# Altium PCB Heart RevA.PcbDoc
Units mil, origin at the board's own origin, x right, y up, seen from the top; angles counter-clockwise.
Board outline 1999.01 x 2099.61 mil, 2 copper layers (Top Copper, Bottom Copper), stack 61.811 mil thick; 52 components, 27 nets, 146 pads, 19 vias.
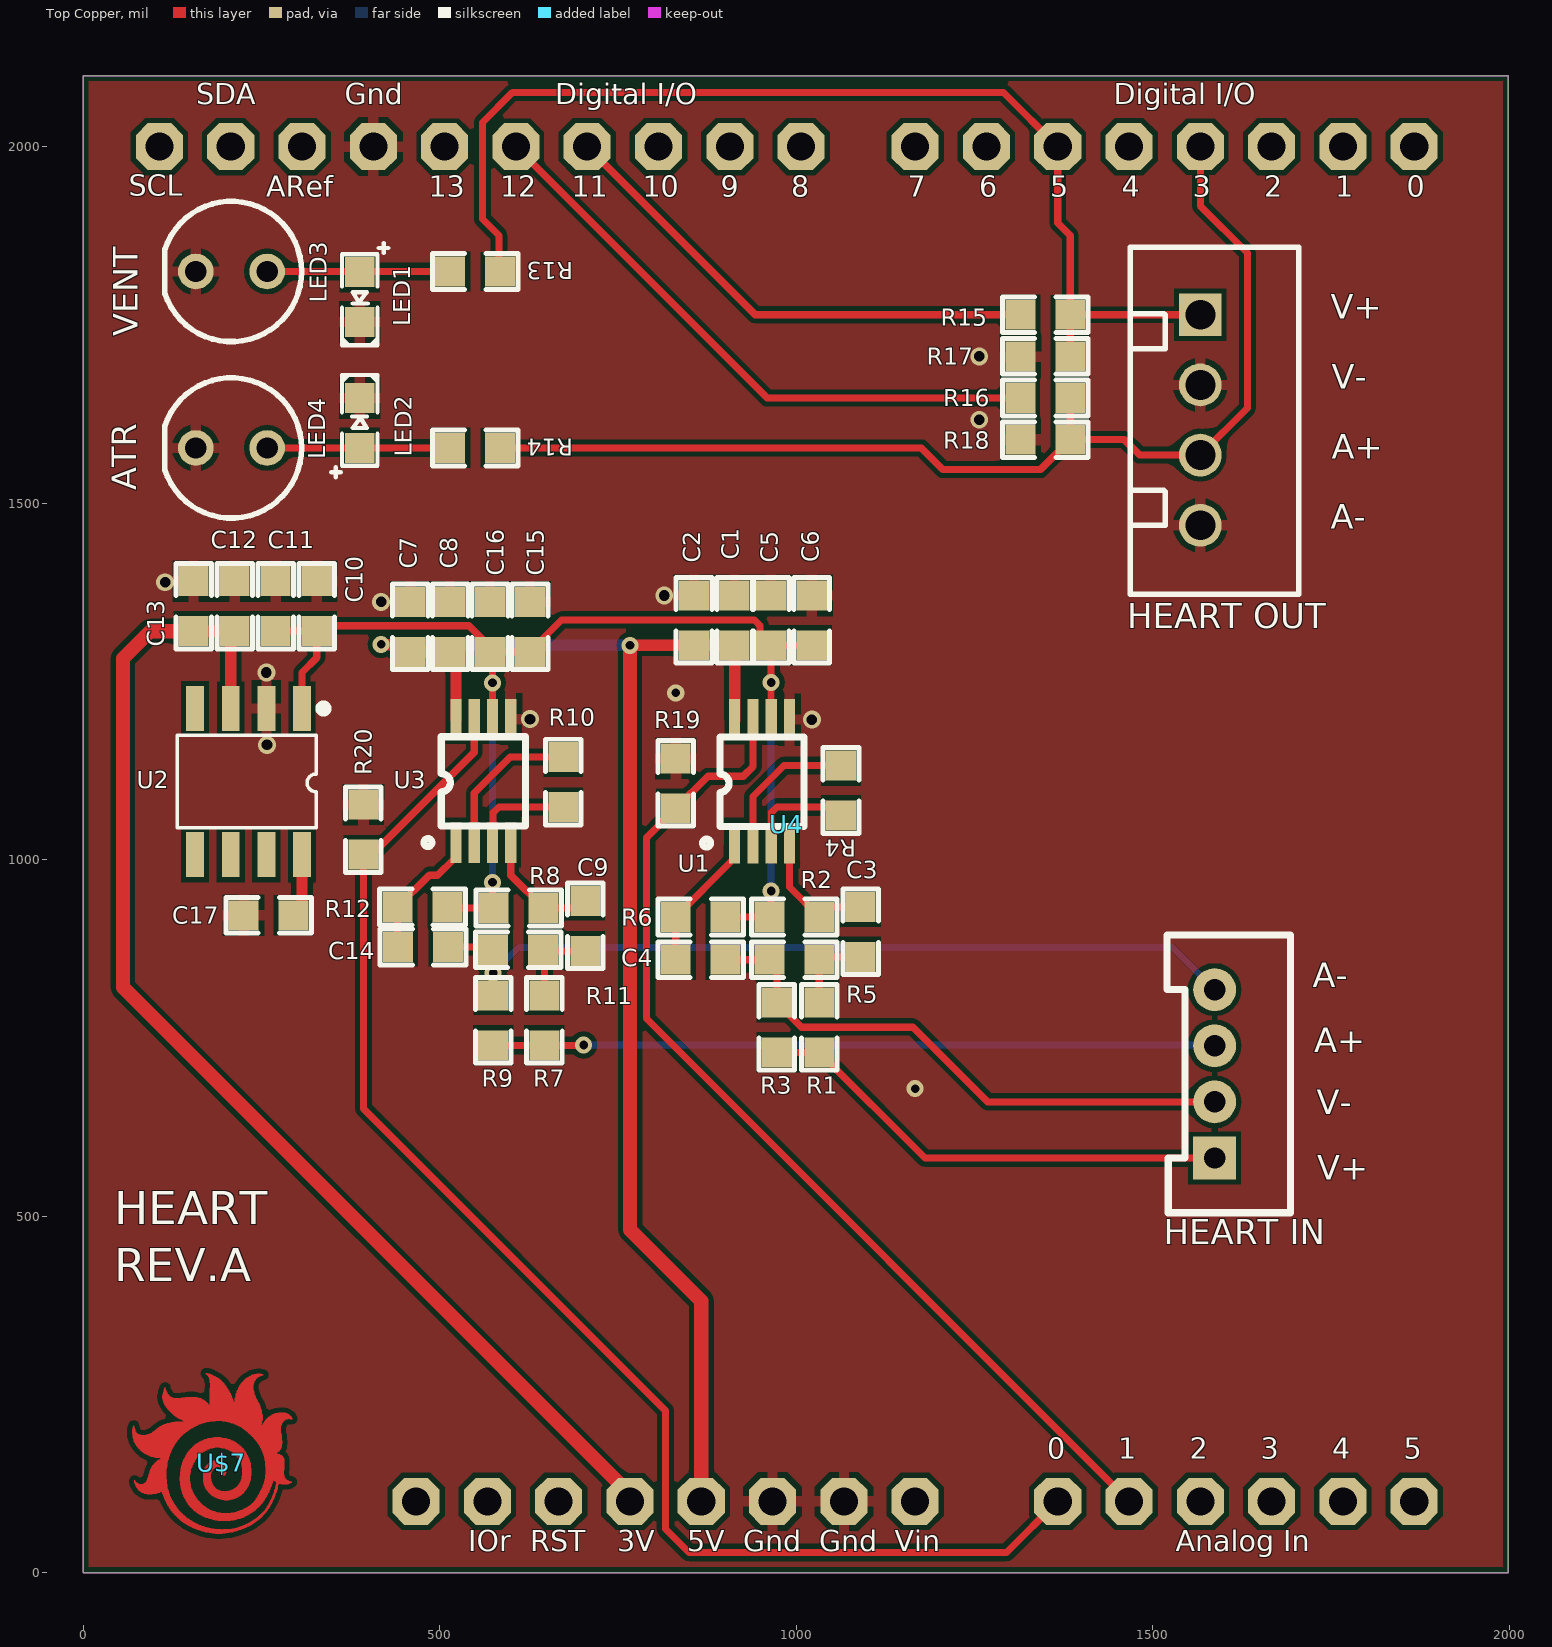
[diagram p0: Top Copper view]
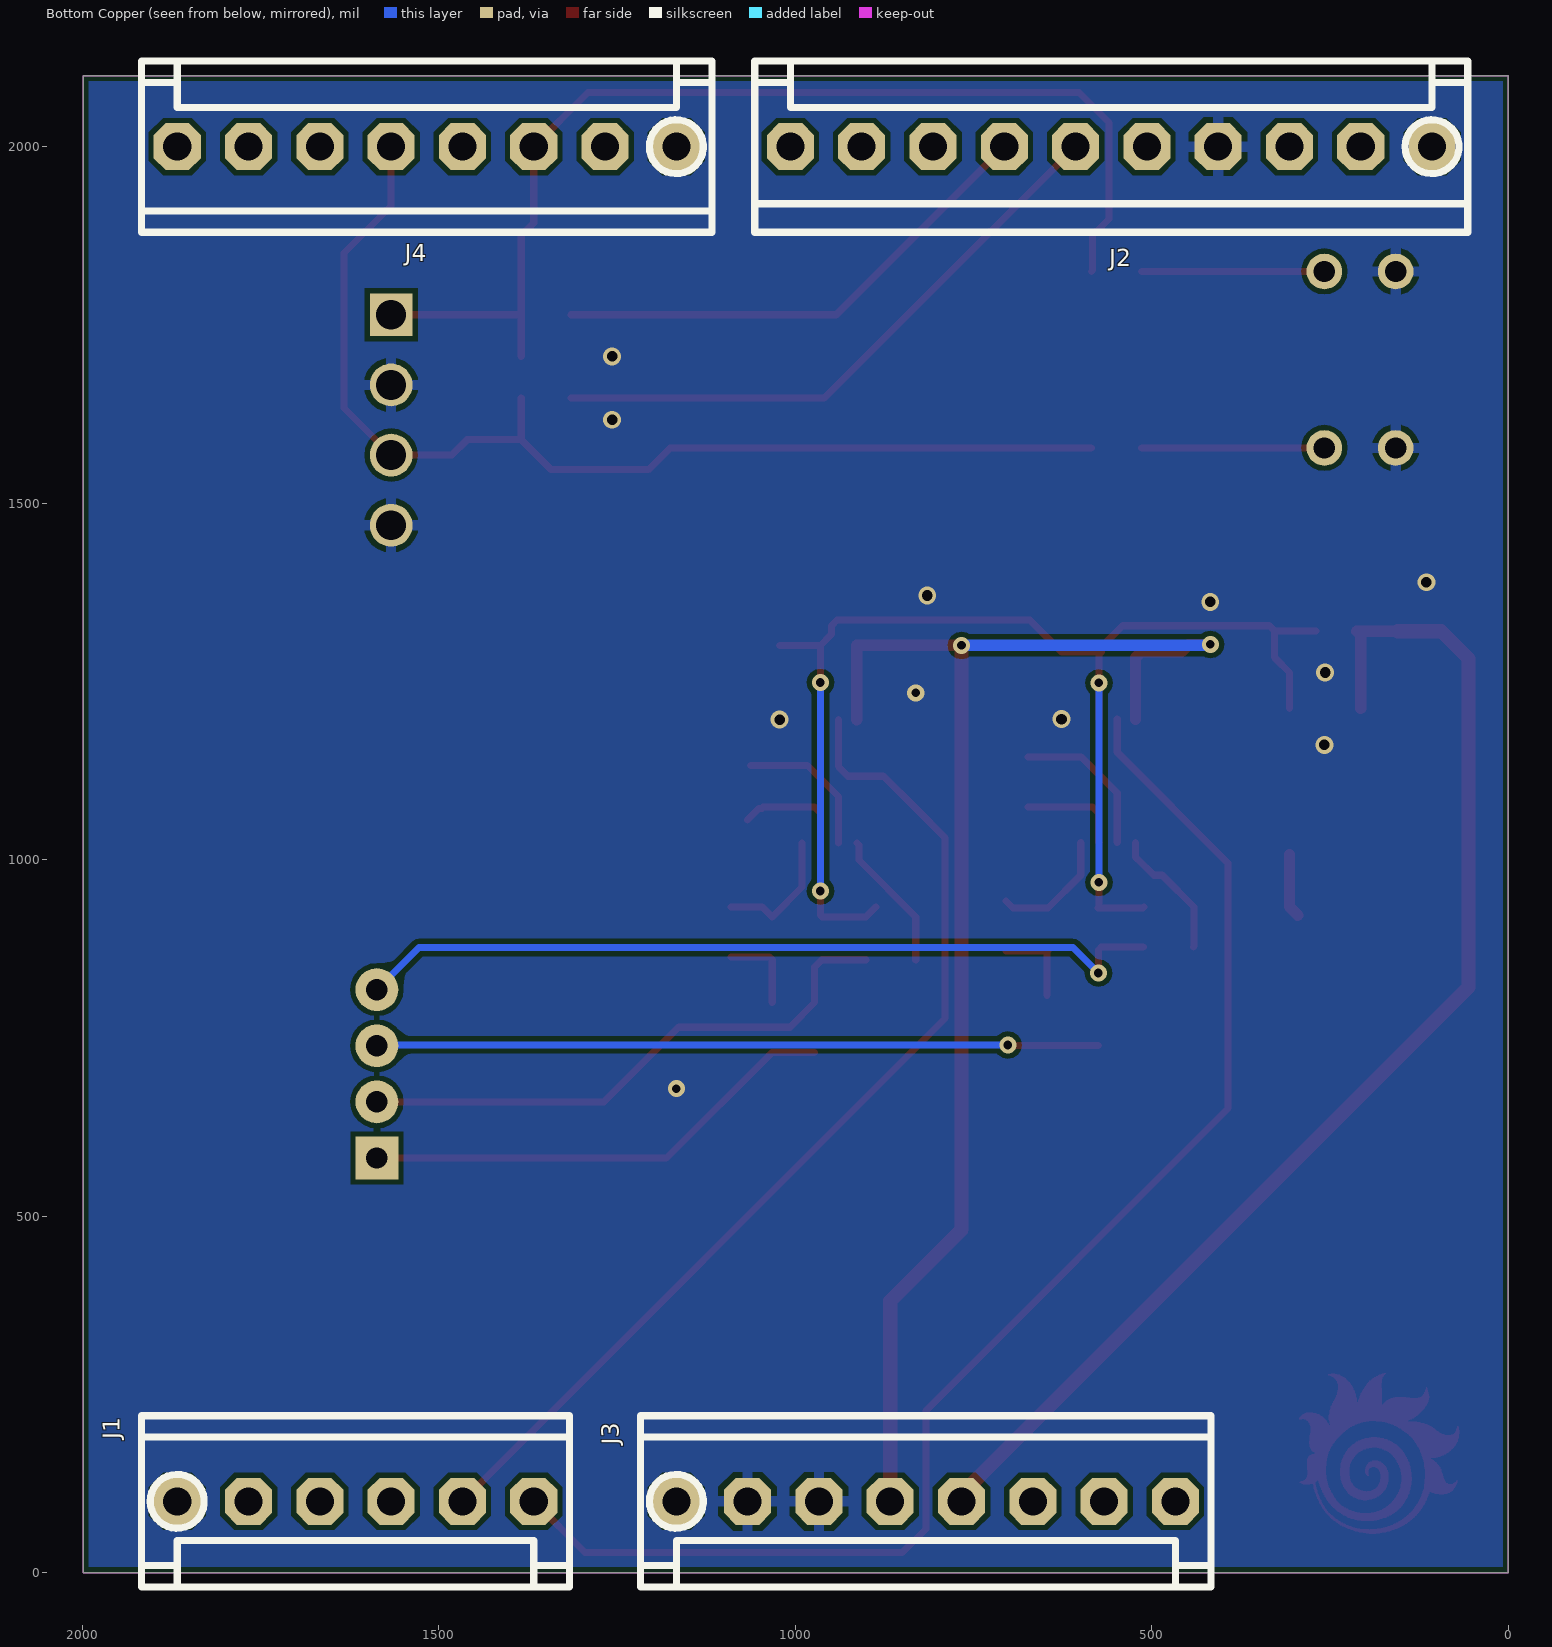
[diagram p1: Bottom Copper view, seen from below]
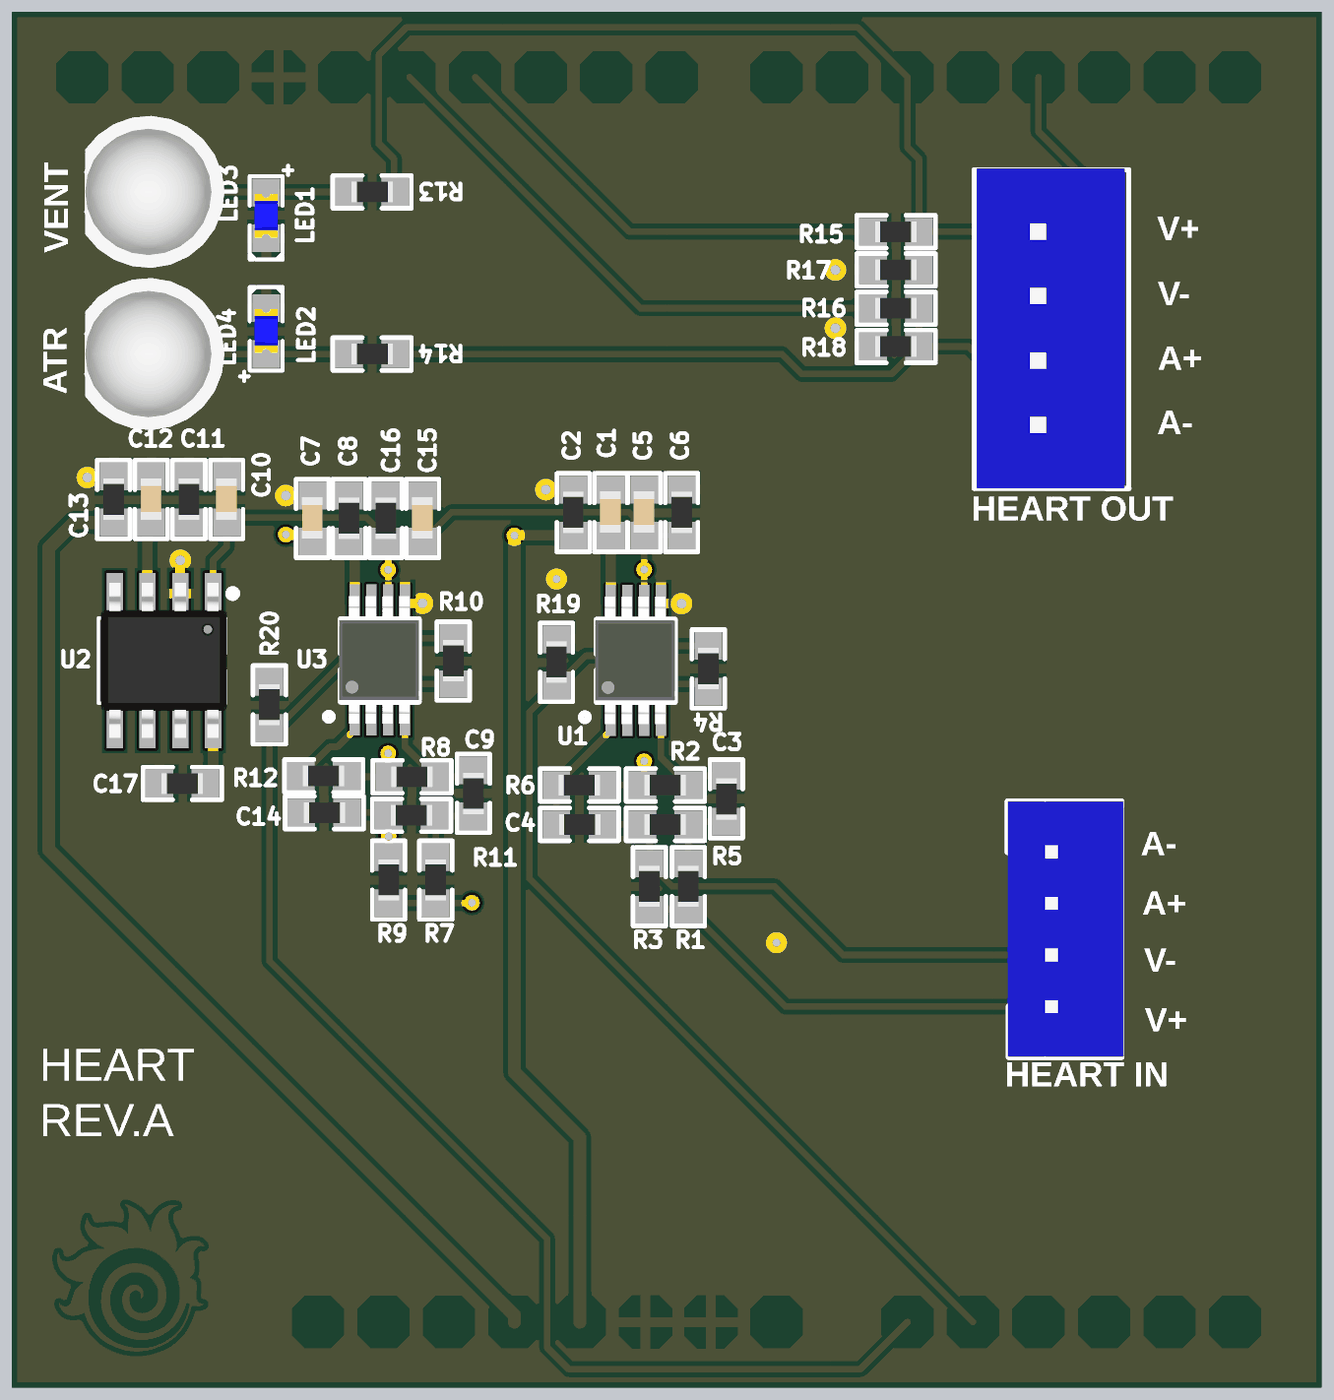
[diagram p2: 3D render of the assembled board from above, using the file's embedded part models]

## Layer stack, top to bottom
Top Mask: solder mask 0.5906, Solder Resist, Dk 3.8
Top Copper: signal copper 1.378
Dielectric 1: prepreg 3.937, 2313, Dk 4.05
Core: core 51.1811, FR-4, Dk 4.5
Dielectric 2: prepreg 3.937, 2313, Dk 4.05
Bottom Copper: signal copper 1.378
Bottom Mask: solder mask 0.5906, Solder Resist, Dk 3.8

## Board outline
0,0 0,2099.61 1999.01,2099.61 1999.01,0

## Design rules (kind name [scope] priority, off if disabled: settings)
AssemblyTestPointUsage [All] p1 off:
AssemblyTestpoint [All] p1 off: testpointundercomponent=TRUE minsize=40 maxsize=100 preferedsize=60 minholesize=0 maxholesize=40 preferedholesize=32 testpointgrid=1 usegrid=TRUE gridtolerance=0.01 allowsidetop=TRUE allowsidebottom=TRUE
Clearance Clearance_poly [InPolygon vs InPolygon] p1: gap=10 ignorepadtopadclearanceinfootprint=FALSE
Clearance [All] p2: gap=7 ignorepadtopadclearanceinfootprint=FALSE
ComponentClearance [All] p1 off: gap=10 collisioncheckmode=3 verticalgap=10 showdistances=FALSE
DiffPairsRouting [All] p1 off: maxlimit=10 minlimit=10 mostfreqgap=10 toplayer_minwidth=15 toplayer_maxwidth=15 toplayer_prefwidth=15 bottomlayer_minwidth=15 bottomlayer_maxwidth=15 bottomlayer_prefwidth=15 maxuncoupledlength=500
FabricationTestPointUsage [All] p1 off: valid=0 allowmultiple=FALSE
FabricationTestpoint [All] p1 off: side=3 testpointundercomponent=TRUE minsize=40 maxsize=100 preferedsize=60 minholesize=0 maxholesize=40 preferedholesize=32 testpointgrid=1 allowsidetop=TRUE allowsidebottom=TRUE usegrid=TRUE gridtolerance=0.01
FanoutControl Fanout_BGA [IsBGA] p1 off: bgadir=Out bgaviamode=Centered fanoutstyle=Auto fanoutdirection=Alternating viagrid=1 // Fanout_BGA (Default Rule)
FanoutControl Fanout_LCC [IsLCC] p2 off: bgadir=Out bgaviamode=Centered fanoutstyle=Auto fanoutdirection=Alternating viagrid=1 // Fanout_LCC (Default Rule)
FanoutControl Fanout_SOIC [IsSOIC] p3 off: bgadir=Out bgaviamode=Centered fanoutstyle=Auto fanoutdirection=Alternating viagrid=1 // Fanout_SOIC (Default Rule)
FanoutControl Fanout_Small [(CompPinCount < 5)] p4 off: bgadir=Out bgaviamode=Centered fanoutstyle=Auto fanoutdirection=OutThenIn viagrid=1 // Fanout_Small (Default Rule)
FanoutControl Fanout_Default [All] p5 off: bgadir=Out bgaviamode=Centered fanoutstyle=Auto fanoutdirection=Alternating viagrid=1 // Fanout_Default (Default Rule)
Height [All] p1 off: minheight=0 maxheight=1000 prefheight=500
HoleSize [All] p1: absolutevalues=TRUE maxlimit=236.22 minlimit=0.98 maxpercent=80.000 minpercent=20.000
MinimumSolderMaskSliver [All] p1 off: minsoldermaskwidth=10
PolygonConnect PolygonConnect_via [IsVia] p1: connectstyle=Direct reliefconductorwidth=10 reliefentries=4 polygonreliefangle="90 Angle" airgapwidth=10
PolygonConnect [All] p2: connectstyle=Relief reliefconductorwidth=15 reliefentries=4 polygonreliefangle="90 Angle" airgapwidth=8
RoutingPriority [All] p1 off: routingpriority=0
RoutingTopology [All] p1 off: topology=Shortest
RoutingVias [All] p1: holewidth=15 width=25 viastyle="Through Hole" minholewidth=12 minwidth=24 maxholewidth=60 maxwidth=80
SilkToSilkClearance [All] p1 off: silktosilkclearance=10
SilkToSolderMaskClearance [IsPad] p1 off: minsilkscreentomaskgap=10 clearancetoexposedcopper=TRUE
SolderMaskExpansion [All] p1: expansion=4 istentingtop=FALSE
UnRoutedNet UnRoutedNet_signal [All] p1:
UnpouredPolygon [All] p1 off:
Width [All] p1: maxlimit=80 minlimit=8 preferedwidth=8
10 further rules are at their usual default settings.

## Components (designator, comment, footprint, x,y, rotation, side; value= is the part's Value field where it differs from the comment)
C1 "0.1uF" 0603_N_1MM 913.79,1370.54 r270 top value=CL10B104KB8NNNL
C2 "1uF" 0603_N 856.74,1370.54 r270 top value=CL10B105KQ8NNNC
C3 "3300pF" 0603_N 1090.5,863.6 r90 top value=885012006016
C4 "3300pF" 0603_N 901.22,859.6 r180 top value=885012006016
C5 "0.1uF" 0603_N_1MM 964.99,1370.54 r270 top value=CL10B104KB8NNNL
C6 "1uF" 0603_N 1022.09,1370.54 r270 top value=CL10B105KQ8NNNC
C7 "0.1uF" 0603_N_1MM 458.73,1361.56 r270 top value=CL10B104KB8NNNL
C8 "1uF" 0603_N 514.73,1361.56 r270 top value=CL10B105KQ8NNNC
C9 "3300pF" 0603_N 704.43,872.02 r90 top value=885012006016
C10 "0.1uF" 0603_N_1MM 327.73,1390.54 r270 top value=CL10B104KB8NNNL
C11 "1uF" 0603_N 270.15,1390.54 r270 top value=CL10B105KQ8NNNC
C12 "0.1uF" 0603_N_1MM 212.57,1390.54 r270 top value=CL10B104KB8NNNL
C13 "1uF" 0603_N 154.99,1390.54 r270 top value=CL10B105KQ8NNNC
C14 "3300pF" 0603_N 511.72,877.48 r180 top value=885012006016
C15 "0.1uF" 0603_N_1MM 626.73,1361.56 r270 top value=CL10B104KB8NNNL
C16 "1uF" 0603_N 570.73,1361.56 r270 top value=CL10B105KQ8NNNC
C17 "1uF" 0603_N 225.15,922.02 r0 top value=CL10B105KQ8NNNC
"HEART IN" "B4B-PH-K-S" B4B-PH-K-S 1587,620.83 r90 top
"HEART OUT" "B4B-XH-A" B4B-XH-A 1567,1764.28 r270 top value=B4B-XH-A(LF)(SN)
J1 "LHS-06-TS" LHS-00-TS_OUTLINE 1867,100 r0 bottom
J2 "LHS-10-TS" LHS-10-TS_OUTLINE 107,2000 r180 bottom
J3 "LHS-08-TS" LHS-08-TS_OUTLINE 1167,100 r0 bottom
J4 "LHS-08-TS" LHS-08-TS_OUTLINE 1167,2000 r180 bottom
LED1 "VLMB1300-GS08" LED_0603 388,1824 r270 top
LED2 "SML-D12V1WT86" LED_0603 388,1577.47 r90 top
LED3 "151051BS04000" LED_5MM 208.2,1825 r0 top
LED4 "151051RS11000" LED_5MM 208.2,1577.47 r0 top
R1 "75K" 0603_N_RES 1032.5,799.6 r270 top value=RC0603FR-0775KL
R2 "162K" 0603_N_RES 962.5,919.6 r0 top value=RC0603FR-07162KL
R3 "1K" 0603_N_RES 973.1,799.6 r270 top value=RC0603FR-071KL
R4 "49.9K" 0603_N_RES 1063,1132 r270 top value=RC0603FR-0749K9L
R5 "49.9K" 0603_N_RES 962.5,859.6 r0 top value=RC0603FR-0749K9L
R6 "162K" 0603_N_RES 831.22,919.6 r0 top value=RC0603FR-07162KL
R7 "75K" 0603_N_RES 647.01,809.48 r270 top value=RC0603FR-0775KL
R8 "162K" 0603_N_RES 575.73,932.22 r0 top value=RC0603FR-07162KL
R9 "1K" 0603_N_RES 575.01,809.48 r270 top value=RC0603FR-071KL
R10 "49.9K" 0603_N_RES 673.6,1143.88 r270 top value=RC0603FR-0749K9L
R11 "49.9K" 0603_N_RES 575.01,873.48 r0 top value=RC0603FR-0749K9L
R12 "162K" 0603_N_RES 441,933.6 r0 top value=RC0603FR-07162KL
R13 "100" 0603_N_RES 584.73,1825 r180 top value=RC0603FR-07100RL
R14 "150" 0603_N_RES 584.73,1577.47 r180 top value=RC0603FR-07150RL
R15 "100K" 0603_N_RES 1314.57,1764.28 r0 top value=RC0603FR-07100KL
R16 "100K" 0603_N_RES 1314.57,1647.47 r0 top value=RC0603FR-07100KL
R17 "1K" 0603_N_RES 1314.57,1705.87 r0 top value=RC0603FR-071KL
R18 "1K" 0603_N_RES 1314.57,1589.06 r0 top value=RC0603FR-071KL
R19 "49.9K" 0603_N_RES 831.22,1142 r270 top value=RC0603FR-0749K9L
R20 "49.9K" 0603_N_RES 393,1077 r270 top value=RC0603FR-0749K9L
U1 "AD8220" MSOP8_0.65mm_DGK 913.81,1023.22 r90 top value=AD8220ARMZ-R7
U2 "TLE2426CDR" SOIC8_SMTC 307,1212 r270 top
U3 "AD8220" MSOP8_0.65mm_DGK 523.01,1023.88 r90 top value=AD8220ARMZ-R7
U4 "ARDUINO_R3" ARDUINOR3 -633,0 r0 top value=n/a
U$7 "" FIREBALL 194,155 r0 top

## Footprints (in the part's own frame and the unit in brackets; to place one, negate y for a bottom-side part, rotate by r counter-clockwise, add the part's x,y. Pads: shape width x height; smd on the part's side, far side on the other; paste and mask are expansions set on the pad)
0603_N [mil]
  rect 42x42 smd mask+0: 1(0,0) 2(70,0)
  silkscreen extent -25,-25 95,25, body extent 3,-16 66,16, height 19
0603_N_1MM [mil] "Full height"
  rect 42x42 smd mask+0: 1(0,0) 2(70,0)
  silkscreen extent -25,-25 95,25, body extent 3,-16 66,15, height 31
0603_N_RES [mil]
  rect 42x42 smd mask+0: 1(0,0) 2(70,0)
  silkscreen extent -25,-25 95,25, body extent 3,-16 66,16, height 19
ARDUINOR3 [mil] "ARDUINOR3"
  oct 66x66 / inner round 0 / far side oct 66x66 hole 39.37: 3V(1400,100) 5V(1500,100) A0(2000,100) A1(2100,100) A2(2200,100) A3(2300,100) A4(2400,100) A5(2500,100) AREF(940,2000) D0(2500,2000) D1(2400,2000) D2(2300,2000) D3(2200,2000) D4(2100,2000) D5(2000,2000) D6(1900,2000) D7(1800,2000) D8(1640,2000) D9(1540,2000) D10(1440,2000) D11(1340,2000) D12(1240,2000) D13(1140,2000) GND(1040,2000) GND1(1700,100) GND2(1600,100) IOREF(1200,100) RESERVED(1100,100) RESET(1300,100) SDA(840,2000) VIN(1800,100)
  oct 66x66 hole 39.37: SCL(740,2000)
B4B-PH-K-S [mil]
  rect 60x60 / inner round 60 / far side rect 60x60 hole 30: 1(-39.37,0)
  round 60 hole 30: 2(39.37,0) 3(118.11,0) 4(196.85,0)
  silkscreen extent -116,-106 274,67, body extent -116,-110 274,67, height 236
B4B-XH-A [mil]
  rect 60x60 hole 42: 1(0,0)
  round 60 hole 42: 2(98.43,0) 3(196.85,0) 4(295.28,0)
  silkscreen extent -94,-98 392,138, body extent -96,-94 392,132, height 276
FIREBALL [mil] "FIREBALL"
  Top Copper drawing of 1562 lines, arcs and shapes, not listed
LED_5MM [mil]
  round 50 hole 30: A(49.8,0) K(-50.2,0)
  silkscreen extent -94,-98 98,98, body extent -96,-116 116,116, height 362
LED_0603 [mil]
  rect 42x42 smd mask+0: A(0,0) K(70,0)
  silkscreen extent -41,-25 102,40, body extent 2,-18 69,18, height 35
LHS-00-TS_OUTLINE [mil]
  silkscreen extent -550,-120 50,120, body extent -555,-125 55,125, height 394
LHS-08-TS_OUTLINE [mil]
  silkscreen extent -750,-120 50,120
LHS-10-TS_OUTLINE [mil]
  silkscreen extent -950,-120 50,120
MSOP8_0.65mm_DGK [mm]
  rect 1.45x0.4 smd: 1(0,0) 2(0,-0.65) 3(0,-1.3) 4(0,-1.95) 5(4.4,-1.95) 6(4.4,-1.3) 7(4.4,-0.65) 8(4.4,0)
  silkscreen extent -0.14,-2.48 3.77,1.14, body extent -0.27,-2.5 4.67,0.6, height 1.1
SOIC8_SMTC [mil]
  rect 63x25 smd: 1(0,0) 2(0,-50) 3(0,-100) 4(0,-150) 5(205,-150) 6(205,-100) 7(205,-50) 8(205,0)
  silkscreen extent -5,-175 167,35, body extent -16,-171 220,21, height 67

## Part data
C1 C5 C7 C10 C12 C15: library part CAP, "CAP CER 0.1UF 50V X7R 0603", Manufacturer=Samsung
C2 C6 C8 C11 C13 C16 C17: library part CAP, "CAP CER 1UF 6.3V X7R 0603", Manufacturer=Samsung
C3 C4 C9 C14: library part CAP, "CAP CER 3300PF 10V C0G/NP0 0603", Manufacturer="Würth Elektronik"
"HEART IN": library part "Header 4", "CONN HEADER VERT 4POS 2MM", Manufacturer=JST
"HEART OUT": library part "Header 4", "CONN HEADER VERT 4POS 2.5MM", Manufacturer=JST
J1: library part "SIP Header 6 Outline", "CONN HEADER VERT 6 POS 2.54MM", Manufacturer="Adam Tech"
J2: library part "SIP Header 10 Outline", "CONN HEADER VERT 10POS 2.54MM", Manufacturer="Adam Tech"
J3 J4: library part "SIP Header 8 Outline", "Header, 8-Pin", Manufacturer="Adam Tech"
LED1: library part LED_1, "LED BLUE HIGHBRIGHT 0603 SMD", Manufacturer=Vishay
LED2: library part LED_1, "Red LED 2.2V 0603", Manufacturer="Rohm Semiconductor"
LED3: library part LED_1, "LED BLUE DIFFUSED 5MM ROUND T/H", Manufacturer="Würth Elektronik"
LED4: library part LED_1, "LED RED DIFFUSED 5MM ROUND T/H", Manufacturer="Würth Elektronik"
R1 R7: library part RES1, "RES SMD 75K OHM 1% 1/10W 0603", Manufacturer=Yageo
R2 R6 R8 R12: library part RES1, "RES SMD 162K OHM 1% 1/10W 0603", Manufacturer=Yageo
R3 R9 R17 R18: library part RES1, "RES SMD 1K OHM 1% 1/10W 0603", Manufacturer=Yageo
R4 R5 R10 R11 R19 R20: library part RES1, "RES SMD 49.9K OHM 1% 1/10W 0603", Manufacturer=Yageo
R13: library part RES1, "RES SMD 100 OHM 1% 1/10W 0603", Manufacturer=Yageo
R14: library part RES1, "RES SMD 150 OHM 1% 1/10W 0603", Manufacturer=Yageo
R15 R16: library part RES1, "RES SMD 100K OHM 1% 1/10W 0603", Manufacturer=Yageo
U1 U3: "IC INST AMP 1 CIRCUIT 8MSOP", Manufacturer="Analog Devices Inc."
U2: library part TLE2426, "IC VREF GND REF 2.0V 1% 8SOIC", Manufacturer="Texas Instruments"
U4: "Arduino R3 Shield", Manufacturer=n/a
U$7: library part FIREBALL

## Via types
v1: diameter 24, hole 12, Top Copper to Bottom Copper, 10 vias
v2: diameter 25, hole 15, Top Copper to Bottom Copper, 9 vias

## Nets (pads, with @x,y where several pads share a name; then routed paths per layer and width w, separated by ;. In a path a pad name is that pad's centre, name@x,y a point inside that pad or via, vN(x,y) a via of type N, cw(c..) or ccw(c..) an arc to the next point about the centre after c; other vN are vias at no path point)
3V3: C12.2 C13.2 U2.3 U4.3V | length 1759.9
  Top Copper w16: C13.2 C12.2 207,1314.97 U2.3
  Top Copper w20: C13.2 94.54,1320.54 56,1282 56,821 767,110 U4.3V
5V0: C1.2 C2.2 C7.2 C8.2 U1.8 U3.8 U4.5V | length 2041.4
  Top Copper w16: v1(418,1302) 418.56,1301.44 448.84,1301.44 C7.2 C8.2 522.99,1283.3 U3.8 ; v1(767,1300.54) C2.2 C1.2 U1.8
  Top Copper w20: v1(767,1300.54) 767,481 867,381 U4.5V
  Bottom Copper w16: v1(418,1302) 419.46,1300.54 v1(767,1300.54)
ADC0: R20.2 U3.7 U4.A0 | length 1969.7
  Top Copper w10: U3.7 548.59,1150.59 393,995 393,651 817,227 817,61 850,28 1295,28 U4.A0
ADC1: R19.2 U1.7 U4.A1 | length 1467.9
  Top Copper w10: U1.7 939.39,1130.39 926,1117 876.22,1117 R19.2 790,1030.78 790,777 U4.A1
ATR+: "HEART IN.3" R7.2 R9.2 | length 1012.6
  Top Copper w10: R9.2 R7.2 701.48,739.48 v1(702,740)
  Bottom Copper w10: v1(702,740) 1585.94,740 1587,738.94
ATR-: "HEART IN.4" C14.1 R9.1 R11.1 | length 1148.7
  Top Copper w10: C14.1 571.01,877.48 R11.1 v1(575,841)
  Bottom Copper w10: v1(575,841) 610.73,876.73 1527.94,876.73 1587,817.68
ATR_NAT: "HEART OUT.3" R14.1 R16.2 R18.2 U4.D3 | length 1566.9
  Top Copper w10: R14.1 1175.53,1577.47 1206,1547 1342.51,1547 R18.2 ; R16.2 R18.2 ; U4.D3 1567,1917 1633,1851 1633,1633.43 1567,1567.43 1481.98,1567.43 1460.35,1589.06 R18.2
GND: "HEART OUT.2" "HEART OUT.4" C1.1 C2.1 C5.1 C6.1 C7.1 C8.1 C10.1 C11.1 C12.1 C13.1 C15.1 C16.1 C17.1 LED1.K LED2.K LED3.K LED4.K R17.1 R18.1 R19.1 R20.1 U1.5 U2.2 U3.5 U4.GND U4.GND1 U4.GND2
  other v1: 1167,678.86 831.22,1234
  other v2: 258,1161 626.73,1197.1 1022.09,1196.44 257,1262.57 418,1361.56 815,1370.54 115,1389 1257,1617 1257,1705.87
NetC3_1: C3.1 R1.1 R5.2 | length 119.7
  Top Copper w10: R1.1 R5.2 1036.5,863.6 C3.1
NetC3_2: C3.2 R2.2 U1.4 | length 184.8
  Top Copper w10: U1.4 990.59,961.5 R2.2 1046.5,933.6 C3.2
NetC4_2: C4.2 R6.1 U1.1 | length 197.8
  Top Copper w10: C4.2 R6.1 910.92,999.3 910.92,1020.34 U1.1
NetC9_1: C9.1 R7.1 R11.2 | length 122.8
  Top Copper w10: R11.2 R11.2@646.47,872.02 ; R7.1 647.01,871.48 R11.2@646.47,872.02 ; C9.1 R11.2@646.47,872.02
NetC9_2: C9.2 R8.2 U3.4 | length 173.4
  Top Copper w10: U3.4 599.79,978.15 R8.2 694.62,932.22 C9.2
NetC14_2: C14.2 R12.1 U3.1 | length 187.9
  Top Copper w10: R12.1 485.55,978.15 497.15,978.15 519.33,1000.33 520.12,1000.33 522.99,1003.2 U3.1 ; R12.1@441.07,933.53 441,933.46 441,878.2 C14.2
NetC17_2: C17.2 U2.8 | length 89.9
  Top Copper w16: C17.2 307,933.87 U2.8
NetLED1_A: LED1.A LED3.A R13.2 | length 256.7
  Top Copper w10: LED3.A 402,1825 R13.2
NetLED2_A: LED2.A LED4.A R14.2 | length 256.7
  Top Copper w10: LED4.A LED2.A R14.2
NetR4_1: R4.1 U1.2 | length 206.9
  Top Copper w10: U1.2 939.39,1088.39 983,1132 R4.1
NetR4_2: R4.2 U1.3 | length 155.3
  Top Copper w10: U1.3 964.99,1065.78 973.1,1073.88 1045.14,1073.88 1047.02,1072 1051,1072 R4.2@1067,1056
NetR10_1: R10.1 U3.2 | length 215.5
  Top Copper w10: U3.2 548.59,1093.4 599.07,1143.88 R10.1
NetR10_2: R10.2 U3.3 | length 144.2
  Top Copper w10: U3.3 575.01,1024.68 575.01,1065.78 583.11,1073.88 R10.2
NetR15_1: R15.1 U4.D11 | length 705.2
  Top Copper w10: U4.D11 942.72,1764.28 R15.1
NetR16_1: R16.1 U4.D12 | length 853.6
  Top Copper w10: U4.D12 959.53,1647.47 R16.1
VENT+: "HEART IN.1" R1.2 R3.2 | length 675.3
  Top Copper w10: R3.2 R1.2 1180.65,581.46 1587,581.46
VENT-: "HEART IN.2" C4.1 R3.1 R5.1 | length 797.3
  Top Copper w10: C4.1 R5.1 973.1,849 R3.1 1007.7,765 1164,765 1268.8,660.2 1587,660.2
VENT_NAT: "HEART OUT.1" R13.1 R15.2 R17.2 U4.D5 | length 1559.2
  Top Copper w10: R13.1 583.11,1826.62 583.11,1875.43 560,1898.54 560,2034 602,2076 1291,2076 U4.D5 1367,1893 1384.57,1875.43 R15.2 ; R17.2 R15.2 ; 1567.2,1764.28 1425,1764.28 R15.2
VREF: C5.2 C6.2 C10.2 C11.2 C15.2 C16.2 R2.1 R6.2 R8.1 R12.2 U1.6 U2.1 U3.6 | length 1916
  Top Copper w10: C11.2 C10.2 ; U2.1 307,1262.57 327.73,1283.3 C10.2 ; R12.2 512.39,932.22 R8.1 574.19,933.75 v1(574.19,968) ; C16.2@569.66,1299.47 541.13,1328 335.19,1328 C10.2 ; U3.6 v1(574.19,1248) 574.19,1288.1 C16.2 C15.2 671.17,1336 941.47,1336 949.36,1328.11 949.36,1316.18 C5.2 ; R6.2@887,933.82 R6.2 R2.1 964.99,922.09 v1(964.99,956) ; U1.6 v1(964.99,1248.49) C5.2 ; C6.2 C5.2
  Bottom Copper w10: v1(574.19,968) v1(574.19,1248) ; v1(964.99,956) v1(964.99,1248.49)
pads on no net: U2.4 U2.5 U2.6 U2.7 U4.A2 U4.A3 U4.A4 U4.A5 U4.AREF U4.D0 U4.D1 U4.D2 U4.D4 U4.D6 U4.D7 U4.D8 U4.D9 U4.D10 U4.D13 U4.IOREF U4.RESERVED U4.RESET U4.SCL U4.SDA U4.VIN

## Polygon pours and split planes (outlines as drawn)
GND on Top Copper "gndtop" (solid, remove dead copper, pour order 3): 0,0 1999.01,0 1999.01,2099.61 0,2099.61
GND on Top Copper "GND_L01_P001" (solid, remove dead copper, pour order 1): -216,21
GND on Bottom Copper "gndtop" (solid, remove dead copper, pour order 4): 0,0 1999.01,0 1999.01,2099.61 0,2099.61

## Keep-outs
Keep-Out Layer:
  the board outline again, w2

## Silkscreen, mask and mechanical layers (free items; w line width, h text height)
Top Overlay:
  text "V+" at 1750,1747.73 h59.06
  text "VENT" at 87.9,1734 h59.06 r90
  text "V-" at 1751,1649.31 h59.06
  text "A+" at 1751,1550.88 h59.06
  text "ATR" at 86,1518 h59.06 r90
  text "A-" at 1750,1452.85 h59.06
  text "A-" at 1725,810 h59.06
  text "A+" at 1727,718.91 h59.06
  text "V-" at 1730,632 h59.06
  text "V+" at 1731,540 h59.06
  text "HEART / REV.A" at 43.74,393 h80
Mechanical 13:
  circle w0.5: c2421.24,137.8 r9.84
  circle w0.5: c137.78,137.8 r9.84
  circle w0.5: c929.51,87.8 r31.5
  circle w0.5: c929.51,187.8 r31.5
  circle w0.5: c329.51,187.8 r31.5
  circle w0.5: c429.51,187.8 r31.5
  circle w0.5: c529.51,187.8 r31.5
  circle w0.5: c629.51,187.8 r31.5
  circle w0.5: c729.51,187.8 r31.5
  circle w0.5: c829.51,187.8 r31.5
  circle w0.5: c1029.51,187.8 r31.5
  circle w0.5: c1129.51,187.8 r31.5
  circle w0.5: c1229.51,187.8 r31.5
  circle w0.5: c1329.51,187.8 r31.5
  circle w0.5: c1429.51,187.8 r31.5
  circle w0.5: c1529.51,187.8 r31.5
  circle w0.5: c1629.51,187.8 r31.5
  circle w0.5: c1729.51,187.8 r31.5
  circle w0.5: c1829.51,187.8 r31.5
  circle w0.5: c1929.51,187.8 r31.5
  circle w0.5: c2029.51,187.8 r31.5
  circle w0.5: c2129.51,187.8 r31.5
  circle w0.5: c329.51,87.8 r31.5
  circle w0.5: c429.51,87.8 r31.5
  circle w0.5: c529.51,87.8 r31.5
  circle w0.5: c629.51,87.8 r31.5
  circle w0.5: c729.51,87.8 r31.5
  circle w0.5: c829.51,87.8 r31.5
  circle w0.5: c1029.51,87.8 r31.5
  circle w0.5: c1129.51,87.8 r31.5
  circle w0.5: c1229.51,87.8 r31.5
  circle w0.5: c1329.51,87.8 r31.5
  circle w0.5: c1429.51,87.8 r31.5
  circle w0.5: c1529.51,87.8 r31.5
  circle w0.5: c1629.51,87.8 r31.5
  circle w0.5: c1729.51,87.8 r31.5
  circle w0.5: c1829.51,87.8 r31.5
  circle w0.5: c1929.51,87.8 r31.5
  circle w0.5: c2029.51,87.8 r31.5
  circle w0.5: c2129.51,87.8 r31.5
  circle w0.5: c2229.51,87.8 r31.5
  circle w0.5: c2421.24,137.8 r9.84
  circle w0.5: c137.78,137.8 r9.84
  circle w0.5: c2421.24,2066.93 r9.84
  circle w0.5: c137.78,2066.93 r9.84
  circle w0.5: c929.51,87.8 r31.5
  circle w0.5: c929.51,187.8 r31.5
  circle w0.5: c329.51,187.8 r31.5
  circle w0.5: c429.51,187.8 r31.5
  circle w0.5: c529.51,187.8 r31.5
  circle w0.5: c629.51,187.8 r31.5
  circle w0.5: c729.51,187.8 r31.5
  circle w0.5: c829.51,187.8 r31.5
  circle w0.5: c1029.51,187.8 r31.5
  circle w0.5: c1129.51,187.8 r31.5
  circle w0.5: c1229.51,187.8 r31.5
  circle w0.5: c1329.51,187.8 r31.5
  circle w0.5: c1429.51,187.8 r31.5
  circle w0.5: c1529.51,187.8 r31.5
  circle w0.5: c1629.51,187.8 r31.5
  circle w0.5: c1729.51,187.8 r31.5
  circle w0.5: c1829.51,187.8 r31.5
  circle w0.5: c1929.51,187.8 r31.5
  circle w0.5: c2029.51,187.8 r31.5
  circle w0.5: c2129.51,187.8 r31.5
  circle w0.5: c329.51,87.8 r31.5
  circle w0.5: c429.51,87.8 r31.5
  circle w0.5: c529.51,87.8 r31.5
  circle w0.5: c629.51,87.8 r31.5
  circle w0.5: c729.51,87.8 r31.5
  circle w0.5: c829.51,87.8 r31.5
  circle w0.5: c1029.51,87.8 r31.5
  circle w0.5: c1129.51,87.8 r31.5
  circle w0.5: c1229.51,87.8 r31.5
  circle w0.5: c1329.51,87.8 r31.5
  circle w0.5: c1429.51,87.8 r31.5
  circle w0.5: c1529.51,87.8 r31.5
  circle w0.5: c1629.51,87.8 r31.5
  circle w0.5: c1729.51,87.8 r31.5
  circle w0.5: c1829.51,87.8 r31.5
  circle w0.5: c1929.51,87.8 r31.5
  circle w0.5: c2029.51,87.8 r31.5
  circle w0.5: c2129.51,87.8 r31.5
  circle w0.5: c2229.51,87.8 r31.5
  lines w0.5: -0.02,118.11 ccw(c118.09,118.11) 118.09,0 ; 2198.02,156.3 2198.02,219.29 ; 2198.02,156.3 2261.01,156.3 ; 2198.02,156.3 2198.02,219.29 ; 2198.02,156.3 2261.01,156.3 ; 2198.02,219.29 2261.01,219.29 ; 2198.02,219.29 2261.01,219.29 ; 2261.01,156.3 2261.01,219.29 ; 2261.01,156.3 2261.01,219.29 ; 279.51,39.37 2279.51,39.37 2279.51,236.22 279.51,236.22 279.51,39.37
Drill Drawing:
  circle w6: c78.69,2772.18 r22.22
  lines w6: 56.46,2494.4 100.91,2494.4 78.69,2449.96 56.46,2494.4 ; 56.46,2561.07 67.57,2561.07 78.69,2549.96 89.8,2561.07 100.91,2561.07 89.8,2572.18 100.91,2583.29 89.8,2583.29 78.69,2594.4 67.57,2583.29 56.46,2583.29 67.57,2572.18 56.46,2561.07 ; 56.46,2649.96 78.69,2661.07 100.91,2649.96 89.8,2672.18 100.91,2694.4 78.69,2683.29 56.46,2694.4 67.57,2672.18 56.46,2649.96 ; 56.46,2849.96 100.91,2849.96 100.91,2894.4 56.46,2894.4 56.46,2849.96
  lines w10: 16.81,2419.96 4720.07,2419.96 ; 16.81,2919.96 4720.07,2919.96 ; 381.93,2319.96 381.93,3019.96 ; 740.5,2319.96 740.5,3019.96 ; 1472.29,2319.96 1472.29,3019.96 ; 1807.41,2319.96 1807.41,3019.96 ; 2294.48,2319.96 2294.48,3019.96 ; 3372.82,2319.96 3372.82,3019.96 ; 3763.92,2319.96 3763.92,3019.96 ; 4258.98,2319.96 4258.98,3019.96 ; 16.81,2319.96 4720.07,2319.96 4720.07,3019.96 16.81,3019.96 16.81,2319.96
  text "Symbol" at 76.81,2949.96 h48
  text "Count" at 411.93,2949.96 h48
  text "Hole Size" at 770.5,2949.96 h48
  text "Plated" at 1502.29,2949.96 h48
  text "Hole Type" at 1837.41,2949.96 h48
  text "Drill Layer Pair" at 2324.48,2949.96 h48
  text "Via/Pad" at 3402.82,2949.96 h48
  text "Pad Shape" at 3793.92,2949.96 h48
  text "Template" at 4288.98,2949.96 h48
  text "4" at 411.93,2849.96 h40
  text "42.00mil (1.067mm)" at 770.5,2849.96 h40
  text "PTH" at 1502.29,2849.96 h40
  text "Round" at 1837.41,2849.96 h40
  text "Top Copper - Bottom Copper" at 2324.48,2849.96 h40
  text "Pad" at 3402.82,2849.96 h40
  text "(Mixed)" at 3793.92,2849.96 h40
  text "(Mixed)" at 4288.98,2849.96 h40
  text "8" at 411.93,2749.96 h40
  text "30.00mil (0.762mm)" at 770.5,2749.96 h40
  text "PTH" at 1502.29,2749.96 h40
  text "Round" at 1837.41,2749.96 h40
  text "Top Copper - Bottom Copper" at 2324.48,2749.96 h40
  text "Pad" at 3402.82,2749.96 h40
  text "Rounded" at 3793.92,2749.96 h40
  text "(Mixed)" at 4288.98,2749.96 h40
  text "9" at 411.93,2649.96 h40
  text "15.00mil (0.381mm)" at 770.5,2649.96 h40
  text "PTH" at 1502.29,2649.96 h40
  text "Round" at 1837.41,2649.96 h40
  text "Top Copper - Bottom Copper" at 2324.48,2649.96 h40
  text "Via" at 3402.82,2649.96 h40
  text "Rounded" at 3793.92,2649.96 h40
  text "v64h38" at 4288.98,2649.96 h40
  text "10" at 411.93,2549.96 h40
  text "12.00mil (0.305mm)" at 770.5,2549.96 h40
  text "PTH" at 1502.29,2549.96 h40
  text "Round" at 1837.41,2549.96 h40
  text "Top Copper - Bottom Copper" at 2324.48,2549.96 h40
  text "Via" at 3402.82,2549.96 h40
  text "Rounded" at 3793.92,2549.96 h40
  text "v61h30" at 4288.98,2549.96 h40
  text "32" at 411.93,2449.96 h40
  text "39.37mil (1.000mm)" at 770.5,2449.96 h40
  text "PTH" at 1502.29,2449.96 h40
  text "Round" at 1837.41,2449.96 h40
  text "Top Copper - Bottom Copper" at 2324.48,2449.96 h40
  text "Pad" at 3402.82,2449.96 h40
  text "(Mixed)" at 3793.92,2449.96 h40
  text "(Mixed)" at 4288.98,2449.96 h40
  text "63 Total" at 411.93,2349.96 h40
